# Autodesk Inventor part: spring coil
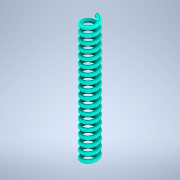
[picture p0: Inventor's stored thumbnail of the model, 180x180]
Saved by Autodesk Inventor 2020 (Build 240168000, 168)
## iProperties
Created: 2020-03
Part Number: spring coil
Material: Generic
Document SubType Name: Modeling
Designer: Darugar
Density: 1 g/cm^3
Appearance: Default
Author: Darugar
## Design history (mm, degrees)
sketch "Sketch1"
  geometry: 1 further point
sketch "Sketch2"
  geometry: L1 (0, 0)-(10, 0); L2 (0.003, 0)-(0.003, -10); C1 r 2.5 at (0.003, -10)
  constraints: 4 end point, 1 centre point, 1 coincident, 1 horizontal
  dimensions: "d0" = 10 distance of L1.start L1.end; "d2" = 10 distance of L2.start L2.end; "d3" = 5 diameter of C1
coil "Coil1" sketch "Sketch2" pitch "d4" = 10; turns "d6" = 18; dims "d5" = 10, "d7" = 0, angle "d8" = 90 deg, angle "d9" = 90 deg, "d10" = 0, "d11" = 0
body "Solid1"
